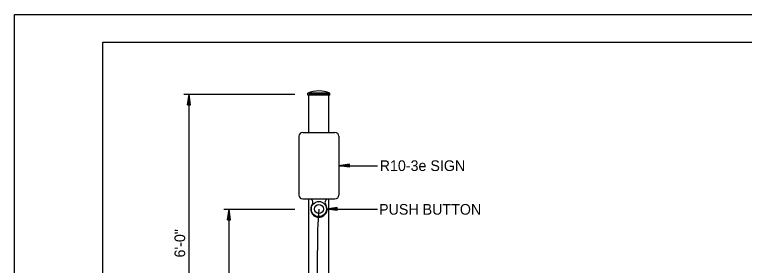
# Model space of a CAD drawing. Extents: x 1369885 to 1370886, y 379976 to 380616.
# Drawn here: x 1369885.5 to 1370193.7, y 380509.6 to 380615.6 of the extents above; entities that cross this region are included whole.
import ezdxf

# ---------------------------------------------------------------- set-up
doc = ezdxf.new("R2010")
doc.units = 0
for name, color, linetype in [('R_Border', 7, 'Continuous'), ('R_Draft', 7, 'Continuous'), ('R_No Plot', 7, 'Continuous')]:
    doc.layers.add(name, color=color, linetype=linetype)

msp = doc.modelspace()

# ---------------------------------------------------------------- linework, layer by layer
at = {"layer": 'R_Border'}
for p, q in [((1369922.71, 380603.9), (1370871.25, 380603.9)), ((1369922.71, 379987.52), (1369922.71, 380603.9))]:
    msp.add_line(p, q, dxfattribs=at)
at = {"layer": 'R_Draft'}
for p, q in [((1369956.92, 380582), (1370003.78, 380582)), ((1369958.5, 380577.5), (1369959.17, 380582)), ((1369958.61, 380577.5), (1369959.17, 380581.25)), ((1369959.17, 380443.41), (1369959.17, 380582)), ((1369959.85, 380577.5), (1369959.17, 380582)), ((1369959.74, 380577.5), (1369959.17, 380581.25)), ((1370018.69, 380582.45), (1370009.35, 380582.45)), ((1370009.35, 380581.55), (1370009.35, 380582.45)), ((1370018.69, 380581.55), (1370009.35, 380581.55)), ((1370018.24, 380582), (1370009.8, 380582)), ((1370009.8, 380565.81), (1370009.8, 380581.55)), ((1370018.24, 380565.81), (1370018.24, 380581.55)), ((1370018.69, 380581.55), (1370018.69, 380582.45)), ((1369958.73, 380577.5), (1369959.17, 380580.48)), ((1369958.84, 380577.5), (1369959.17, 380579.73)), ((1369958.95, 380577.5), (1369959.17, 380578.97)), ((1369959.07, 380577.5), (1369959.17, 380578.21)), ((1369959.62, 380577.5), (1369959.17, 380580.48)), ((1369959.51, 380577.5), (1369959.17, 380579.73)), ((1369959.39, 380577.5), (1369959.17, 380578.97)), ((1369959.28, 380577.5), (1369959.17, 380578.21)), ((1369958.5, 380577.5), (1369959.85, 380577.5)), ((1370007.22, 380565.81), (1370020.81, 380565.81)), ((1370005.58, 380564.17), (1370005.58, 380539.32)), ((1370022.45, 380564.17), (1370022.45, 380539.32)), ((1370026.95, 380552.42), (1370022.45, 380551.74)), ((1370022.45, 380551.74), (1370038.75, 380551.74)), ((1370026.95, 380551.07), (1370022.45, 380551.74)), ((1370026.95, 380552.31), (1370023.21, 380551.74)), ((1370026.95, 380551.18), (1370023.21, 380551.74)), ((1370026.95, 380552.19), (1370023.98, 380551.74)), ((1370026.95, 380551.3), (1370023.98, 380551.74)), ((1370026.95, 380552.08), (1370024.73, 380551.74)), ((1370026.95, 380551.41), (1370024.73, 380551.74)), ((1370026.95, 380551.97), (1370025.49, 380551.74)), ((1370026.95, 380551.53), (1370025.49, 380551.74)), ((1370026.95, 380551.85), (1370026.24, 380551.74)), ((1370026.95, 380551.64), (1370026.24, 380551.74)), ((1370026.95, 380551.07), (1370026.95, 380552.42)), ((1370007.22, 380537.68), (1370020.81, 380537.68)), ((1370009.8, 380447), (1370009.8, 380537.68)), ((1370018.24, 380447), (1370018.24, 380537.68)), ((1369973.8, 380533.41), (1370003.78, 380533.41)), ((1369975.37, 380528.91), (1369976.05, 380533.41)), ((1369975.49, 380528.91), (1369976.05, 380532.66)), ((1369975.6, 380528.91), (1369976.05, 380531.88)), ((1369976.05, 380443.41), (1369976.05, 380533.41)), ((1369976.72, 380528.91), (1369976.05, 380533.41)), ((1369976.61, 380528.91), (1369976.05, 380532.66)), ((1369976.5, 380528.91), (1369976.05, 380531.88)), ((1370021.7, 380534.08), (1370017.2, 380533.41)), ((1370017.2, 380533.41), (1370038.75, 380533.41)), ((1370021.7, 380532.73), (1370017.2, 380533.41)), ((1370021.7, 380533.97), (1370017.96, 380533.41)), ((1370021.7, 380532.84), (1370017.96, 380533.41)), ((1370021.7, 380533.85), (1370018.73, 380533.41)), ((1370021.7, 380532.96), (1370018.73, 380533.41)), ((1370021.7, 380533.74), (1370019.48, 380533.41)), ((1370021.7, 380533.07), (1370019.48, 380533.41)), ((1370021.7, 380533.63), (1370020.24, 380533.41)), ((1370021.7, 380533.19), (1370020.24, 380533.41)), ((1370021.7, 380533.51), (1370020.99, 380533.41)), ((1370021.7, 380533.3), (1370020.99, 380533.41)), ((1370021.7, 380532.73), (1370021.7, 380534.08)), ((1369975.37, 380528.91), (1369976.72, 380528.91)), ((1369975.71, 380528.91), (1369976.05, 380531.13)), ((1369975.83, 380528.91), (1369976.05, 380530.37)), ((1369975.94, 380528.91), (1369976.05, 380529.62)), ((1369976.38, 380528.91), (1369976.05, 380531.13)), ((1369976.27, 380528.91), (1369976.05, 380530.37)), ((1369976.15, 380528.91), (1369976.05, 380529.62)), ((1370013.45, 380416.95), (1370013.45, 380515.9))]:
    msp.add_line(p, q, dxfattribs=at)
for radius in [3.19, 1.88]:
    msp.add_circle((1370014.02, 380533.41), radius, dxfattribs=at)
for centre, radius, start, end in [((1370014.02, 380570.79), 12.56, 68.1777, 111.8223), ((1370007.22, 380564.17), 1.64, 90, 180), ((1370020.81, 380564.17), 1.64, 0, 90), ((1370007.22, 380539.32), 1.64, 180, 270), ((1370020.81, 380539.32), 1.64, 270, 0), ((1370009.88, 380536.26), 1.58, 318.1972, 64.8044), ((1370014.02, 380533.41), 3.47, 148.7402, 31.2598), ((1370018.16, 380536.26), 1.57, 115.1956, 221.8028), ((1370137.83, 380520.67), 124.47, 174.1251, 182.1939)]:
    msp.add_arc(centre, radius, start, end, dxfattribs=at)
at = {"layer": 'R_No Plot'}
msp.add_line((1369885.51, 380615.59), (1370885.51, 380615.59), dxfattribs=at)
msp.add_lwpolyline([(1369885.49, 380615.59), (1370885.51, 380615.59), (1370885.51, 379975.58), (1369885.49, 379975.58)], close=True, dxfattribs=at)

# ---------------------------------------------------------------- texts
at = {"layer": 'R_Draft'}
for s, p in [('R10-3e SIGN', (1370039.69, 380549.49)), ('PUSH BUTTON', (1370039.45, 380531.03))]:
    msp.add_text(s, height=4.5, dxfattribs=at).set_placement(p)
msp.add_text('6\'-0"', height=4.5, rotation=90, dxfattribs=at).set_placement((1369957.53, 380512.94))

doc.saveas('drawing.dxf')
